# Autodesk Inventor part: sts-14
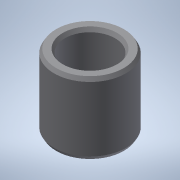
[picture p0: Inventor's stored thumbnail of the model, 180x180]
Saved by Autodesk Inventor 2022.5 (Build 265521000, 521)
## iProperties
Created: 2016-12
Part Number: sts-14
Material: 一般
Document SubType Name: Modeling
Designer: imaocorp
Density: 1 g/cm^3
Appearance: 既定
Author: imaocorp
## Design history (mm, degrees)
node "sts-14.x_t1"
node "sts-14"
node "Base1"
